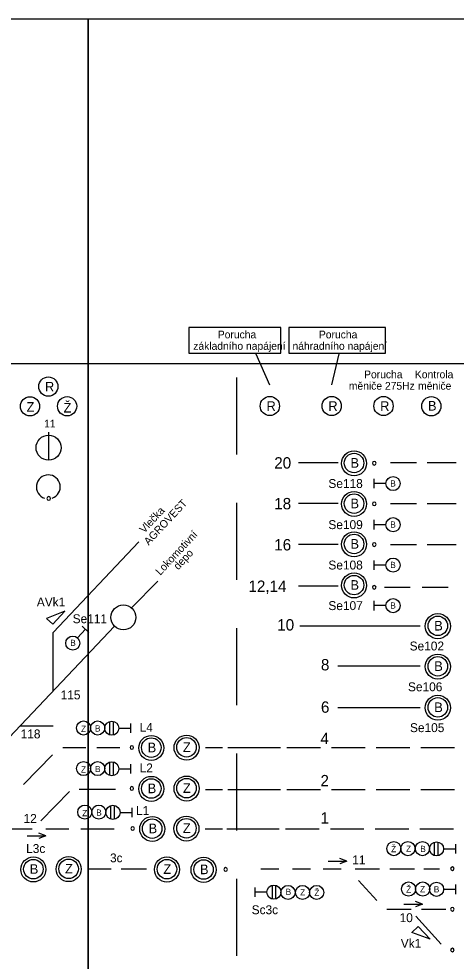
# Model space of a CAD drawing. Extents: x 0 to 840, y 0 to 297.
# Drawn here: x 196.5 to 281.5, y 113.8 to 297 of the extents above; entities that cross this region are included whole.
import ezdxf

# ---------------------------------------------------------------- set-up
doc = ezdxf.new("R2010")
doc.units = 0
for name, color, linetype in [('formát tisku', 7, 'Continuous'), ('KOLEJIŠTĚ', 7, 'Continuous'), ('KOLEJOVÉ_DESKY', 7, 'Continuous')]:
    doc.layers.add(name, color=color, linetype=linetype)

# ---------------------------------------------------------------- blocks, each defined once
blk = doc.blocks.new('KONTROLKAR_P')
at = {"layer": 'KOLEJOVÉ_DESKY'}
blk.add_circle((-0.004, -0.001), 0.54, dxfattribs=at)
blk.add_text('R', height=0.54, dxfattribs=at).set_placement((-0.193, -0.274))
blk = doc.blocks.new('KONTROLKAB_P')
at = {"layer": 'KOLEJOVÉ_DESKY'}
blk.add_circle((0.004, 0.002), 0.54, dxfattribs=at)
blk.add_text('B', height=0.54, dxfattribs=at).set_placement((-0.186, -0.243))
blk = doc.blocks.new('TLAČÍTKO_P1')
at = {"layer": 'KOLEJOVÉ_DESKY'}
for centre, radius, start, end in [((-0.026, -0.02), 0.671, 289.1317, 252.1427), ((0.001, -0.67), 0.1, 0, 180), ((0.001, -0.67), 0.1, 180, 0)]:
    blk.add_arc(centre, radius, start, end, dxfattribs=at)
blk = doc.blocks.new('KONTROLKAZ_P')
at = {"layer": 'KOLEJOVÉ_DESKY'}
blk.add_circle((-0.016, 0.001), 0.54, dxfattribs=at)
blk.add_text('Z', height=0.54, dxfattribs=at).set_placement((-0.206, -0.302))
blk = doc.blocks.new('KONTROLKAŽ_P')
at = {"layer": 'KOLEJOVÉ_DESKY'}
blk.add_circle((-0.002, 0.005), 0.54, dxfattribs=at)
blk.add_text('Ž', height=0.54, dxfattribs=at).set_placement((-0.201, -0.349))
blk = doc.blocks.new('ŘADIČ_P')
at = {"layer": 'KOLEJOVÉ_DESKY'}
blk.add_line((0.009, 0.934), (0.009, -0.602), dxfattribs=at)
blk.add_circle((0.009, 0.053), 0.703, dxfattribs=at)
for name, p in [('KONTROLKAR_P', (0, 3.487)), ('KONTROLKAZ_P', (-1.02, 2.376)), ('KONTROLKAŽ_P', (1.053, 2.376))]:
    blk.add_blockref(name, p, dxfattribs=at)
blk = doc.blocks.new('TLAČÍTKOB')
at = {"layer": 'KOLEJOVÉ_DESKY'}
for centre, radius in [((-0.004, -0.026), 0.703), ((-0.004, -0.007), 0.548)]:
    blk.add_circle(centre, radius, dxfattribs=at)
blk.add_text('B', height=0.54, dxfattribs=at).set_placement((-0.206, -0.27))
blk = doc.blocks.new('TEČKA')
at = {"layer": 'KOLEJOVÉ_DESKY'}
for start, end in [(0, 180), (180, 0)]:
    blk.add_arc((0, 0), 0.1, start, end, dxfattribs=at)
blk = doc.blocks.new('NÁV1S_P')
at = {"layer": 'KOLEJOVÉ_DESKY'}
for p, q in [((-0.002, -0.266), (-0.002, 0.263)), ((0.659, -0.001), (-0.002, -0.001))]:
    blk.add_line(p, q, dxfattribs=at)
blk.add_circle((1.056, -0.001), 0.397, dxfattribs=at)
blk = doc.blocks.new('ŠIPKA_MALÁ')
at = {"layer": 'KOLEJOVÉ_DESKY'}
for p, q in [((-0.011, 0.001), (0.392, 0.152)), ((-0.011, 0.002), (0.392, -0.149)), ((1.047, 0.001), (0.004, 0.001))]:
    blk.add_line(p, q, dxfattribs=at)
blk = doc.blocks.new('VU1')
blk.add_lwpolyline([(-3, 0), (3, 0), (-3, 3)], close=True)
blk = doc.blocks.new('TLAČÍTKOZ')
at = {"layer": 'KOLEJOVÉ_DESKY'}
for centre, radius in [((-0.001, -0.008), 0.703), ((-0.001, 0.011), 0.548)]:
    blk.add_circle(centre, radius, dxfattribs=at)
blk.add_text('Z', height=0.54, dxfattribs=at).set_placement((-0.203, -0.252))
blk = doc.blocks.new('DĚL_ČÁR')
at = {"layer": 'KOLEJOVÉ_DESKY'}
for p, q in [((0, 0), (0, -0.1733)), ((0, -0.2817), (0, -0.455)), ((0, -0.5634), (0, -0.7367)), ((0, -0.8451), (0, -1.0184)), ((0, -1.1268), (0, -1.3001)), ((0, -1.4085), (0, -1.5818)), ((0, -1.6901), (0, -1.8635))]:
    blk.add_line(p, q, dxfattribs=at)

msp = doc.modelspace()

# ---------------------------------------------------------------- linework, layer by layer
for p, q in [((210, 297), (210, 288.11)), ((96.97, 230), (522.5, 230))]:
    msp.add_line(p, q)
at = {"layer": 'formát tisku'}
for points in [[(0, 297), (210, 297), (210, 0), (0, 0)], [(210, 297), (420, 297), (420, 0), (210, 0)]]:
    msp.add_lwpolyline(points, close=True, dxfattribs=at)
at = {"layer": 'KOLEJIŠTĚ'}
for p, q in [((242.56, 231.89), (245.25, 225.88)), ((258.75, 231.89), (257.27, 225.88))]:
    msp.add_line(p, q, dxfattribs=at)
for points in [[(229.57, 236.98), (229.57, 232.02), (247.47, 232.02), (247.47, 236.98)], [(249.01, 236.98), (249.01, 232.02), (267.77, 232.02), (267.77, 236.98)]]:
    msp.add_lwpolyline(points, close=True, dxfattribs=at)
at = {"layer": 'KOLEJOVÉ_DESKY'}
for p, q in [((258.62, 210.73), (250.9, 210.73)), ((268.79, 210.79), (273.81, 210.79)), ((268.79, 210.79), (273.81, 210.79)), ((275.92, 210.79), (281.52, 210.79)), ((275.92, 210.79), (281.52, 210.79)), ((258.62, 202.8), (250.9, 202.8)), ((268.79, 202.79), (273.81, 202.79)), ((275.92, 202.79), (281.52, 202.79)), ((203.17, 177.71), (219.81, 195.35)), ((258.62, 194.81), (250.9, 194.81)), ((268.79, 194.85), (273.81, 194.85)), ((275.92, 194.85), (281.52, 194.85)), ((218.42, 182.5), (223.52, 187.68)), ((258.62, 186.75), (250.9, 186.75)), ((267.58, 186.51), (272.6, 186.51)), ((274.95, 186.51), (279.97, 186.51)), ((185.18, 147.42), (215.1, 178.95)), ((203.17, 166.37), (203.17, 177.71)), ((274.57, 178.93), (251.17, 178.93)), ((274.57, 171.18), (258.53, 171.18)), ((274.57, 163.09), (258.53, 163.09)), ((196.73, 159.6), (203.17, 159.6)), ((214.16, 157.83), (214.16, 160.43)), ((214.89, 157.83), (214.89, 160.43)), ((197.42, 148.18), (203.03, 153.92)), ((205.02, 155.34), (209.54, 155.34)), ((211.63, 155.34), (216.14, 155.34)), ((232.81, 155.34), (236.09, 155.34)), ((237.15, 155.34), (247.35, 155.34)), ((248.59, 155.34), (255.13, 155.34)), ((257.29, 155.34), (263.83, 155.34)), ((265.99, 155.34), (272.53, 155.34)), ((274.69, 155.34), (281.23, 155.34)), ((214.16, 149.94), (214.16, 152.54)), ((214.89, 149.94), (214.89, 152.54)), ((200.75, 141.09), (206.35, 146.83)), ((208.22, 147.25), (215.31, 147.25)), ((232.81, 147.18), (236.09, 147.18)), ((237.15, 147.18), (247.35, 147.18)), ((248.59, 147.18), (255.13, 147.18)), ((257.29, 147.18), (263.83, 147.18)), ((265.99, 147.18), (272.53, 147.18)), ((274.69, 147.18), (281.23, 147.18)), ((214.39, 141.47), (214.39, 144.06)), ((215.12, 141.47), (215.12, 144.06)), ((195.18, 139.53), (199.09, 139.53)), ((201.73, 139.53), (206.24, 139.53)), ((208.56, 139.53), (215, 139.53)), ((232.72, 139.53), (236.09, 139.53)), ((236.93, 139.53), (247.12, 139.53)), ((248.37, 139.53), (254.91, 139.53)), ((257.07, 139.53), (263.61, 139.53)), ((265.77, 139.53), (272.31, 139.53)), ((274.47, 139.53), (281.01, 139.53)), ((277.33, 134.38), (277.33, 136.97)), ((278.05, 134.38), (278.05, 136.97)), ((210.02, 131.78), (214.44, 131.78)), ((216.39, 131.78), (221.33, 131.78)), ((243.56, 131.78), (247.08, 131.78)), ((249.7, 131.78), (253.21, 131.78)), ((255.65, 131.78), (259.16, 131.78)), ((261.87, 131.78), (266.61, 131.78)), ((268.67, 131.78), (273.41, 131.78)), ((275.25, 131.78), (278.27, 131.78)), ((245.77, 128.53), (245.77, 125.94)), ((246.45, 125.95), (246.45, 128.55)), ((262.52, 129.52), (266.09, 125.64)), ((268.07, 123.93), (272.81, 123.93)), ((274.78, 123.93), (279.52, 123.93)), ((273.7, 122.58), (278.62, 117.11))]:
    msp.add_line(p, q, dxfattribs=at)
for centre, radius in [((216.83, 180.66), 2.43), ((209.07, 159.16), 1.37), ((211.82, 159.16), 1.37), ((209.07, 151.28), 1.37), ((211.82, 151.28), 1.37), ((209.31, 142.8), 1.37), ((212.05, 142.8), 1.37), ((269.42, 135.71), 1.37), ((272.16, 135.71), 1.37), ((274.98, 135.71), 1.37), ((248.84, 127.2), 1.37), ((251.67, 127.2), 1.37), ((254.41, 127.2), 1.37), ((272.29, 127.86), 1.37), ((275.03, 127.86), 1.37)]:
    msp.add_circle(centre, radius, dxfattribs=at)

# ---------------------------------------------------------------- block references
at = {"layer": 'KOLEJIŠTĚ', "xscale": 86.48488649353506, "yscale": 86.48488649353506}
msp.add_blockref('DĚL_ČÁR', (238.85, 227.31), dxfattribs=at)
at = {"layer": 'KOLEJOVÉ_DESKY', "xscale": 3.459395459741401, "yscale": 3.4593954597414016}
for name, p in [('ŘADIČ_P', (202.24, 213.46)), ('KONTROLKAR_P', (245.32, 221.75)), ('KONTROLKAR_P', (257.35, 221.75)), ('KONTROLKAR_P', (267.42, 221.75)), ('KONTROLKAB_P', (276.7, 221.69)), ('TLAČÍTKOB', (261.7, 210.69)), ('TEČKA', (265.61, 210.62)), ('TLAČÍTKO_P1', (202.31, 206.1)), ('NÁV1S_P', (265.61, 206.67)), ('TLAČÍTKOB', (261.7, 202.8)), ('TEČKA', (265.61, 202.73)), ('NÁV1S_P', (265.61, 198.68)), ('TLAČÍTKOB', (261.7, 194.95)), ('TEČKA', (265.61, 194.81)), ('NÁV1S_P', (265.61, 190.82)), ('TLAČÍTKOB', (261.7, 186.96)), ('TEČKA', (265.61, 186.51)), ('NÁV1S_P', (265.61, 182.94)), ('TLAČÍTKOB', (277.99, 179.04)), ('TLAČÍTKOB', (277.99, 171.18)), ('TLAČÍTKOB', (277.99, 163.19)), ('TLAČÍTKOB', (222.26, 155.37)), ('TLAČÍTKOZ', (229.11, 155.37)), ('TEČKA', (218.46, 155.37)), ('TLAČÍTKOB', (222.26, 147.42)), ('TLAČÍTKOZ', (229.11, 147.42)), ('TEČKA', (218.46, 147.41)), ('TLAČÍTKOB', (222.44, 139.63)), ('TLAČÍTKOZ', (229.09, 139.63)), ('TEČKA', (218.63, 139.63)), ('TLAČÍTKOB', (199.33, 131.75)), ('TLAČÍTKOZ', (206.18, 131.75)), ('TLAČÍTKOZ', (225.3, 131.68)), ('TLAČÍTKOB', (232.43, 131.68)), ('TEČKA', (236.71, 131.67)), ('TEČKA', (280.8, 131.82)), ('NÁV1S_P', (242.44, 127.25)), ('TEČKA', (280.8, 123.93)), ('TEČKA', (280.8, 116.01))]:
    msp.add_blockref(name, p, dxfattribs=at)
at = {"layer": 'KOLEJOVÉ_DESKY'}
for name, p, xscale, yscale, rotation in [('VU1', (204.27, 180.59), 0.5667873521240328, 0.5667873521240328, 47.78996823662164), ('NÁV1S_P', (209.46, 178.35), 3.459395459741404, 3.459395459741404, -132.47331218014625), ('NÁV1S_P', (218.22, 159.11), 3.459395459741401, 3.4593954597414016, 180), ('NÁV1S_P', (218.22, 151.22), 3.459395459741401, 3.4593954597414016, 180), ('NÁV1S_P', (218.45, 142.75), 3.459395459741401, 3.4593954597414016, 180), ('ŠIPKA_MALÁ', (201.71, 138.22), 3.459395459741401, 3.4593954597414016, 180), ('NÁV1S_P', (281.38, 135.66), 3.459395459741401, 3.4593954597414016, 180), ('ŠIPKA_MALÁ', (260.25, 133.27), 3.459395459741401, 3.4593954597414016, 180), ('NÁV1S_P', (281.38, 127.8), 3.459395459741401, 3.4593954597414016, 180), ('ŠIPKA_MALÁ', (274.98, 124.9), 3.459395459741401, 3.4593954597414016, 180), ('VU1', (275.33, 119.36), 0.5667873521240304, -0.5667873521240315, -46.6986692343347)]:
    msp.add_blockref(name, p, dxfattribs=dict(at, xscale=xscale, yscale=yscale, rotation=rotation))

# ---------------------------------------------------------------- texts
for s, height, p in [('Porucha', 1.5, (235.19, 234.89)), ('Porucha', 1.5, (254.85, 234.89)), ('základního napájení', 1.5, (230.41, 232.67)), ('náhradního napájení', 1.5, (249.71, 232.67)), ('Porucha', 1.5, (263.64, 227.14)), ('Kontrola', 1.5, (273.52, 227.14)), ('měniče 275Hz', 1.5, (260.67, 224.92)), ('měniče', 1.5, (274.14, 224.92)), ('11', 1.494, (201.41, 217.57)), ('20', 2.214, (246.16, 209.58)), ('Se118', 1.73, (256.69, 205.81)), ('B', 1.21, (268.72, 206.09)), ('18', 2.214, (246.16, 201.66)), ('Se109', 1.73, (256.69, 197.82)), ('B', 1.21, (268.72, 198.1)), ('16', 2.214, (246.16, 193.67)), ('Se108', 1.73, (256.69, 189.97)), ('B', 1.21, (268.72, 190.25)), ('12,14', 2.214, (241.14, 185.61)), ('AVk1', 1.73, (199.99, 182.79)), ('Se107', 1.73, (256.69, 182.08)), ('B', 1.21, (268.72, 182.36)), ('Se111', 1.73, (206.96, 179.53)), ('10', 2.214, (246.74, 178.1)), ('B', 1.21, (206.48, 175.11)), ('Se102', 1.73, (272.49, 174.23)), ('8', 2.21, (255.24, 170.35)), ('Se106', 1.73, (272.17, 166.3)), ('115', 1.73, (204.62, 164.72)), ('6', 2.21, (255.24, 162.12)), ('Z', 1.21, (208.58, 158.39)), ('B', 1.21, (211.3, 158.47)), ('L4', 1.73, (219.98, 158.42)), ('Se105', 1.73, (272.56, 158.36)), ('118', 1.73, (196.84, 157.14)), ('4', 2.21, (255.15, 156.02)), ('L2', 1.73, (219.98, 150.53)), ('Z', 1.21, (208.58, 150.5)), ('B', 1.21, (211.3, 150.58)), ('2', 2.21, (255.15, 147.82)), ('Z', 1.21, (208.82, 142.02)), ('B', 1.21, (211.53, 142.11)), ('L1', 1.73, (219.29, 142.26)), ('12', 1.73, (197.41, 140.71)), ('1', 2.21, (255.15, 140.57)), ('L3c', 1.73, (197.91, 134.86)), ('Ž', 1.21, (268.88, 135.02)), ('Z', 1.21, (271.79, 135.09)), ('B', 1.21, (274.56, 135.05)), ('3c', 1.702, (214.24, 133.06)), ('11', 1.73, (261.32, 132.65)), ('Ž', 1.21, (271.81, 127.16)), ('Z', 1.21, (274.51, 127.23)), ('B', 1.21, (277.19, 127.2)), ('B', 1.21, (248.39, 126.71)), ('Z', 1.21, (251.2, 126.61)), ('Ž', 1.21, (253.94, 126.51)), ('Sc3c', 1.73, (241.77, 122.96)), ('10', 1.73, (270.54, 121.42)), ('Vk1', 1.73, (270.77, 116.44))]:
    msp.add_text(s, height=height, dxfattribs=at).set_placement(p)
for s, p in [('AGROVEST', (221.75, 194.59)), ('Vlečka', (220.88, 196.91)), ('Lokomotivní', (224, 188.73)), ('depo', (227.49, 189.79))]:
    msp.add_text(s, height=1.5, rotation=47.0156, dxfattribs=at).set_placement(p)

doc.saveas('drawing.dxf')
